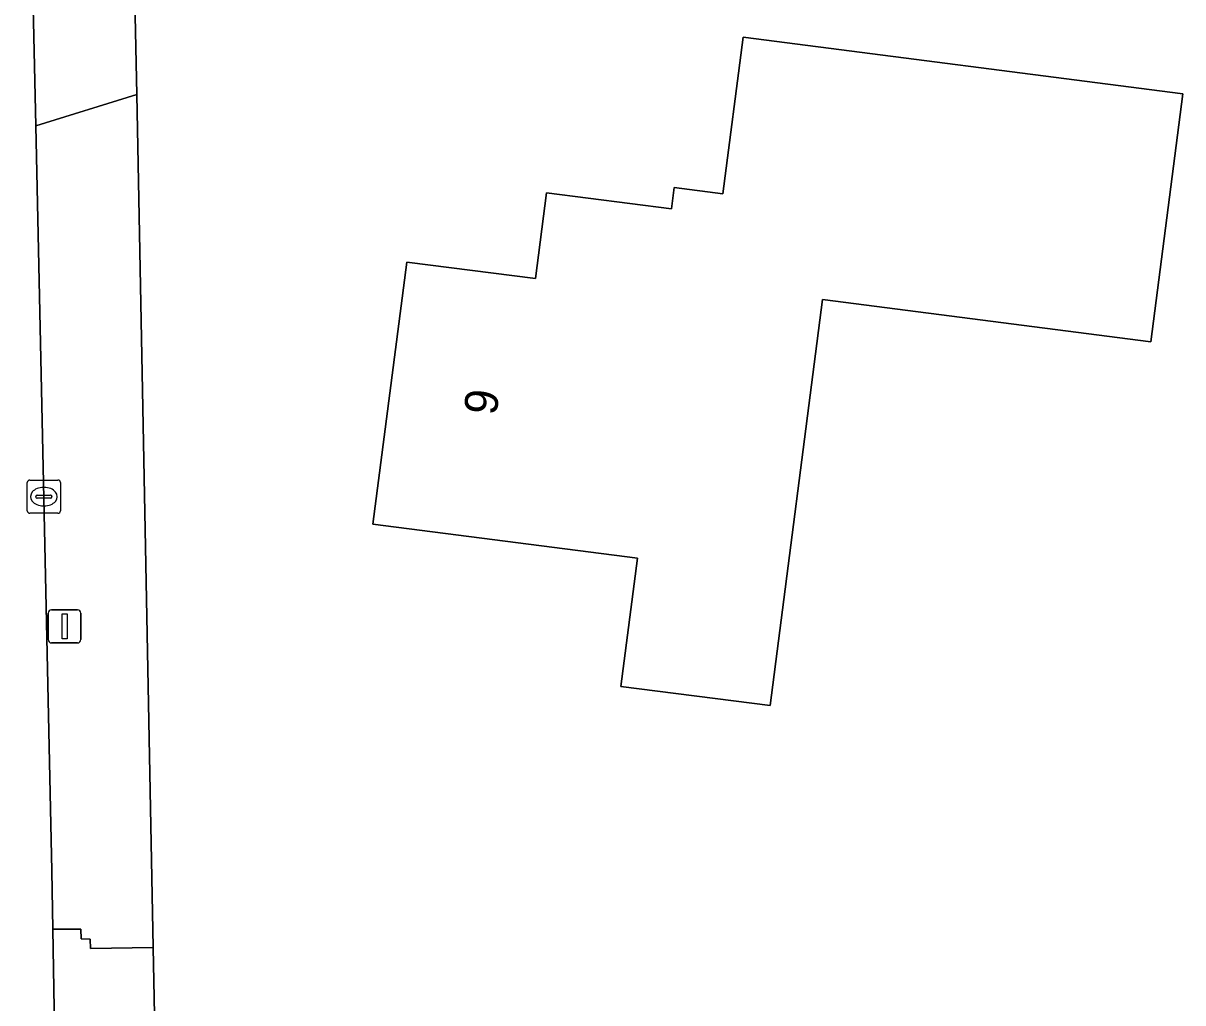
# Model space of a CAD drawing. Extents: x 161258 to 161838, y 380833 to 381727.
# Drawn here: x 161656.63 to 161691.62, y 381194.91 to 381224.48 of the extents above; entities that cross this region are included whole.
import ezdxf

# ---------------------------------------------------------------- set-up
doc = ezdxf.new("R2010")
doc.units = 0
for name, color, linetype in [('IMGEO_Erf', 7, 'Continuous'), ('IMGEO_Kolk', 7, 'Continuous'), ('IMGEO_Lichtmast', 7, 'Continuous'), ('IMGEO_Pand', 7, 'Continuous'), ('IMGEO_Pand_nummerreeks', 7, 'Continuous'), ('IMGEO_Rijbaan_lokaal_open', 7, 'Continuous'), ('IMGEO_Voetpad_open', 7, 'Continuous')]:
    doc.layers.add(name, color=color, linetype=linetype)

msp = doc.modelspace()

# ---------------------------------------------------------------- linework, layer by layer
at = {"layer": 'IMGEO_Erf'}
msp.add_lwpolyline([(161660.762, 381266.569), (161660.073, 381256.315), (161659.92, 381252.625), (161659.847, 381249.958), (161659.857, 381232.624), (161660.002, 381225.178), (161660.058, 381222.332), (161660.56, 381196.578), (161660.619, 381193.545), (161660.796, 381184.49), (161661.214, 381177.248), (161661.514, 381175.703), (161662, 381174.206), (161663.26, 381172.033), (161664.355, 381170.597), (161665.625, 381169.313)], dxfattribs=at)
msp.add_lwpolyline([(161691.625, 381222.348), (161690.657, 381214.86), (161680.754, 381216.141), (161679.173, 381203.883), (161674.671, 381204.464), (161675.17, 381208.332), (161667.184, 381209.358), (161668.205, 381217.273), (161672.093, 381216.772), (161672.426, 381219.361), (161676.195, 381218.875), (161676.278, 381219.519), (161677.746, 381219.33), (161678.356, 381224.064)], close=True, dxfattribs=at)
at = {"layer": 'IMGEO_Kolk'}
for p, q in [((161656.756, 381209.765), (161656.756, 381210.617)), ((161656.831, 381210.691), (161657.683, 381210.691)), ((161657.757, 381210.617), (161657.757, 381209.765)), ((161657.015, 381210.185), (161657.015, 381210.197)), ((161657.058, 381210.234), (161657.456, 381210.234)), ((161657.244, 381210.471), (161657.269, 381210.471)), ((161657.499, 381210.197), (161657.499, 381210.185)), ((161657.453, 381210.148), (161657.055, 381210.148)), ((161657.267, 381209.911), (161657.242, 381209.911)), ((161657.683, 381209.691), (161656.831, 381209.691))]:
    msp.add_line(p, q, dxfattribs=at)
for points in [[(161656.756, 381209.765), (161656.756, 381210.617)], [(161656.831, 381210.691), (161657.683, 381210.691)], [(161657.757, 381210.617), (161657.757, 381209.765)], [(161657.683, 381209.691), (161656.831, 381209.691)]]:
    msp.add_lwpolyline(points, dxfattribs=at)
for centre, radius, start, end in [((161656.833, 381210.615), 0.0765, 91.552, 178.448), ((161656.833, 381210.615), 0.0765, 91.552, 178.448), ((161657.681, 381210.615), 0.0765, 1.552, 88.448), ((161657.681, 381210.615), 0.0765, 1.552, 88.448), ((161657.055, 381210.194), 0.0403, 85.8775, 175.7526), ((161657.46, 381210.196), 0.0386, 1.7309, 96.639), ((161657.052, 381210.184), 0.0366, 178.938, 274.7102), ((161657.456, 381210.191), 0.043, 264.8664, 352.4533), ((161656.833, 381209.767), 0.0765, 181.552, 268.448), ((161656.833, 381209.767), 0.0765, 181.552, 268.448), ((161657.681, 381209.767), 0.0765, 271.552, 358.448), ((161657.681, 381209.767), 0.0765, 271.552, 358.448)]:
    msp.add_arc(centre, radius, start, end, dxfattribs=at)
for centre, major_axis, ratio, start_param, end_param in [((161657.243, 381210.191), (-0.387, 0.002), 0.722429, 4.712389, 7.853982), ((161657.268, 381210.191), (-0.39, 0.002), 0.717154, 1.570796, 4.712389)]:
    msp.add_ellipse(centre, major_axis=major_axis, ratio=ratio, start_param=start_param, end_param=end_param, dxfattribs=at)
at = {"layer": 'IMGEO_Lichtmast'}
for p, q in [((161657.485, 381206.775), (161658.275, 381206.775)), ((161658.275, 381206.775), (161657.485, 381206.775)), ((161657.385, 381205.875), (161657.385, 381206.675)), ((161657.385, 381206.675), (161657.385, 381205.875)), ((161658.375, 381206.675), (161658.375, 381205.875)), ((161658.375, 381205.875), (161658.375, 381206.675)), ((161658.275, 381205.775), (161657.485, 381205.775)), ((161657.485, 381205.775), (161658.275, 381205.775))]:
    msp.add_line(p, q, dxfattribs=at)
msp.add_lwpolyline([(161657.805, 381206.65), (161657.955, 381206.65), (161657.955, 381205.9), (161657.805, 381205.9), (161657.805, 381206.65)], dxfattribs=at)
for centre, start, end in [((161657.485, 381206.675), 90, 180), ((161657.485, 381206.675), 90, 180), ((161658.275, 381206.675), 0, 90), ((161658.275, 381206.675), 360, 90), ((161657.485, 381205.875), 180, 270), ((161657.485, 381205.875), 180, 270), ((161658.275, 381205.875), 270, 0), ((161658.275, 381205.875), 270, 0)]:
    msp.add_arc(centre, 0.1, start, end, dxfattribs=at)
at = {"layer": 'IMGEO_Pand'}
msp.add_lwpolyline([(161691.625, 381222.348), (161678.356, 381224.064), (161677.746, 381219.33), (161676.278, 381219.519), (161676.195, 381218.875), (161672.426, 381219.361), (161672.093, 381216.772), (161668.205, 381217.273), (161667.184, 381209.358), (161675.17, 381208.332), (161674.671, 381204.464), (161679.173, 381203.883), (161680.754, 381216.141), (161690.657, 381214.86)], close=True, dxfattribs=at)
at = {"layer": 'IMGEO_Rijbaan_lokaal_open'}
msp.add_lwpolyline([(161657.941, 381178.467), (161657.878, 381179.14), (161657.784, 381183.884), (161657.637, 381190.821), (161657.6, 381192.937), (161657.527, 381197.132), (161657.496, 381198.896), (161657.016, 381221.388), (161656.949, 381224.532), (161656.9, 381226.01), (161656.661, 381233.168), (161656.633, 381235.807), (161656.639, 381237.026), (161656.634, 381242.223), (161656.651, 381245.83), (161656.712, 381249.982), (161656.8, 381253.735)], dxfattribs=at)
at = {"layer": 'IMGEO_Voetpad_open'}
for points in [[(161660.002, 381225.178), (161656.9, 381226.01), (161656.949, 381224.532), (161657.016, 381221.388), (161660.058, 381222.332)], [(161660.058, 381222.332), (161657.016, 381221.388), (161657.496, 381198.896), (161657.527, 381197.132), (161658.374, 381197.131), (161658.385, 381196.841), (161658.659, 381196.829), (161658.664, 381196.553), (161660.56, 381196.578)], [(161660.56, 381196.578), (161658.664, 381196.553), (161658.659, 381196.829), (161658.385, 381196.841), (161658.374, 381197.131), (161657.527, 381197.132), (161657.6, 381192.937), (161658.485, 381192.937), (161658.485, 381193.235), (161659.075, 381193.245), (161659.075, 381193.553), (161660.619, 381193.545)]]:
    msp.add_lwpolyline(points, close=True, dxfattribs=at)

# ---------------------------------------------------------------- texts
at = {"layer": 'IMGEO_Pand_nummerreeks'}
msp.add_text('9', height=1, rotation=82.6492, dxfattribs=at).set_placement((161670.913, 381212.621))

doc.saveas('drawing.dxf')
